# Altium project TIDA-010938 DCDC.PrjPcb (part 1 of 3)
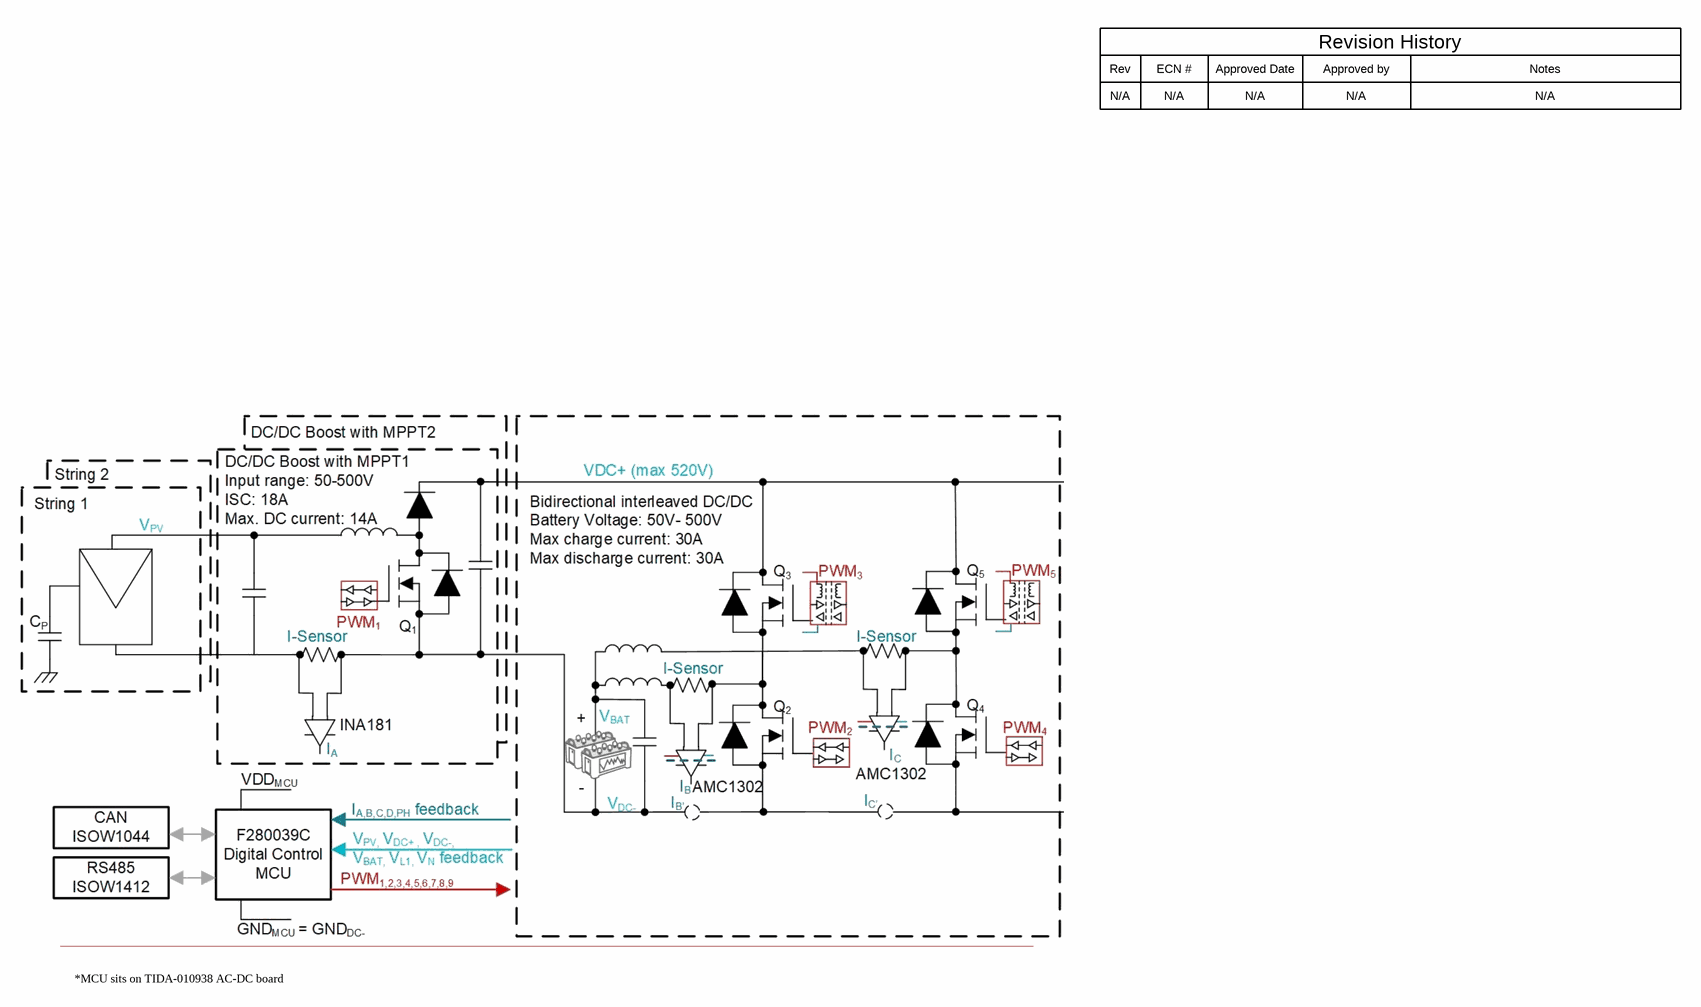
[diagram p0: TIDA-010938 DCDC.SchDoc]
CopyrightYear: 2024; PCB_Layout: Vedatroyee Ghosh; PCB_Rev: E2; PRJ_Customer: Public Release; PRJ_Engineer: Vedatroyee Ghosh; PRJ_Number: TIDA-010938 DC-DC; PRJ_Title: TIDA-010938 DC-DC; SCH_Rev: E2; TechSupport: http://www.ti.com/support; TID: A0498176
9 sheets, 410 parts. Net scope: flat (ports and power ports of the same name join across sheets).
Board file: TIDA-010938 DCDC.PcbDoc
Sheets:
  TIDA-010938 DCDC.SchDoc
    Designator = TIDA-010938 DCDC_Top.SchDoc
      Designator = TIDA-010938 DC-DC_Boost1.SchDoc
      Designator = TIDA-010938 DC-DC_Boost2.SchDoc
      Designator = TIDA-010938 bidirectional DC-DC_Interleaved1.SchDoc
      Designator = TIDA-010938 DC-DC_VoltageMeasurement.SchDoc
      Designator = TIDA-010938 DC-DC_Data conditionning.SchDoc
      Designator = TIDA-010938 bidirectional DC-DC_Interleaved2.SchDoc
      Designator = TIDA-010938 DCDC_Hardware.SchDoc

## Sheet TIDA-010938 DCDC.SchDoc
size 431 x 279 mm; Date: Not shown in title block; ApprovedBy: Not shown in title block; CheckedBy: Not shown in title block; Author: Not shown in title block; CompanyName: Not shown in title block; Engineer: Not shown in title block; Organization: Not shown in title block; Address1: Not shown in title block; Address2: Not shown in title block; Address3: Not shown in title block; Address4: Not shown in title block; DocumentNumber: 1; Revision: Use project parameter SCH_Rev; SheetNumber: 1; SheetTotal: 9; PageSetup: Record=PageOptions¦CenterHorizontal=True¦CenterVertical=True¦PrintScale=1.00¦XCorrection=1.00¦YCorrection=1.00¦PrintKind=0¦BorderSize=5000000¦LeftOffset=0¦BottomOffset=0¦Orientation=2¦PaperLength=1000¦PaperWidth=1000¦Scale=100¦PaperSource=15¦PrintQuality=600¦MediaType=1¦DitherType=10¦PaperKind=Letter¦PrintScaleMode=1

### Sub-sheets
Designator = TIDA-010938 DCDC_Top.SchDoc: no entries

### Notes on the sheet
- Rev
- N/A
- ECN #
- Approved Date
- Approved by
- Revision History
- Notes
- *MCU sits on TIDA-010938 AC-DC board

## Sheet TIDA-010938 DCDC_Top.SchDoc
size 431 x 279 mm; Date: Not shown in title block; ApprovedBy: Not shown in title block; CheckedBy: Not shown in title block; Author: Not shown in title block; CompanyName: Not shown in title block; Engineer: Not shown in title block; Organization: Not shown in title block; Address1: Not shown in title block; Address2: Not shown in title block; Address3: Not shown in title block; Address4: Not shown in title block; DocumentNumber: 1; Revision: Use project parameter SCH_Rev; SheetNumber: 2; SheetTotal: 9; PageSetup: Record=PageOptions¦CenterHorizontal=True¦CenterVertical=True¦PrintScale=1.00¦XCorrection=1.00¦YCorrection=1.00¦PrintKind=0¦BorderSize=5000000¦LeftOffset=0¦BottomOffset=0¦Orientation=2¦PaperLength=1000¦PaperWidth=1000¦Scale=100¦PaperSource=15¦PrintQuality=600¦MediaType=1¦DitherType=10¦PaperKind=Letter¦PrintScaleMode=1
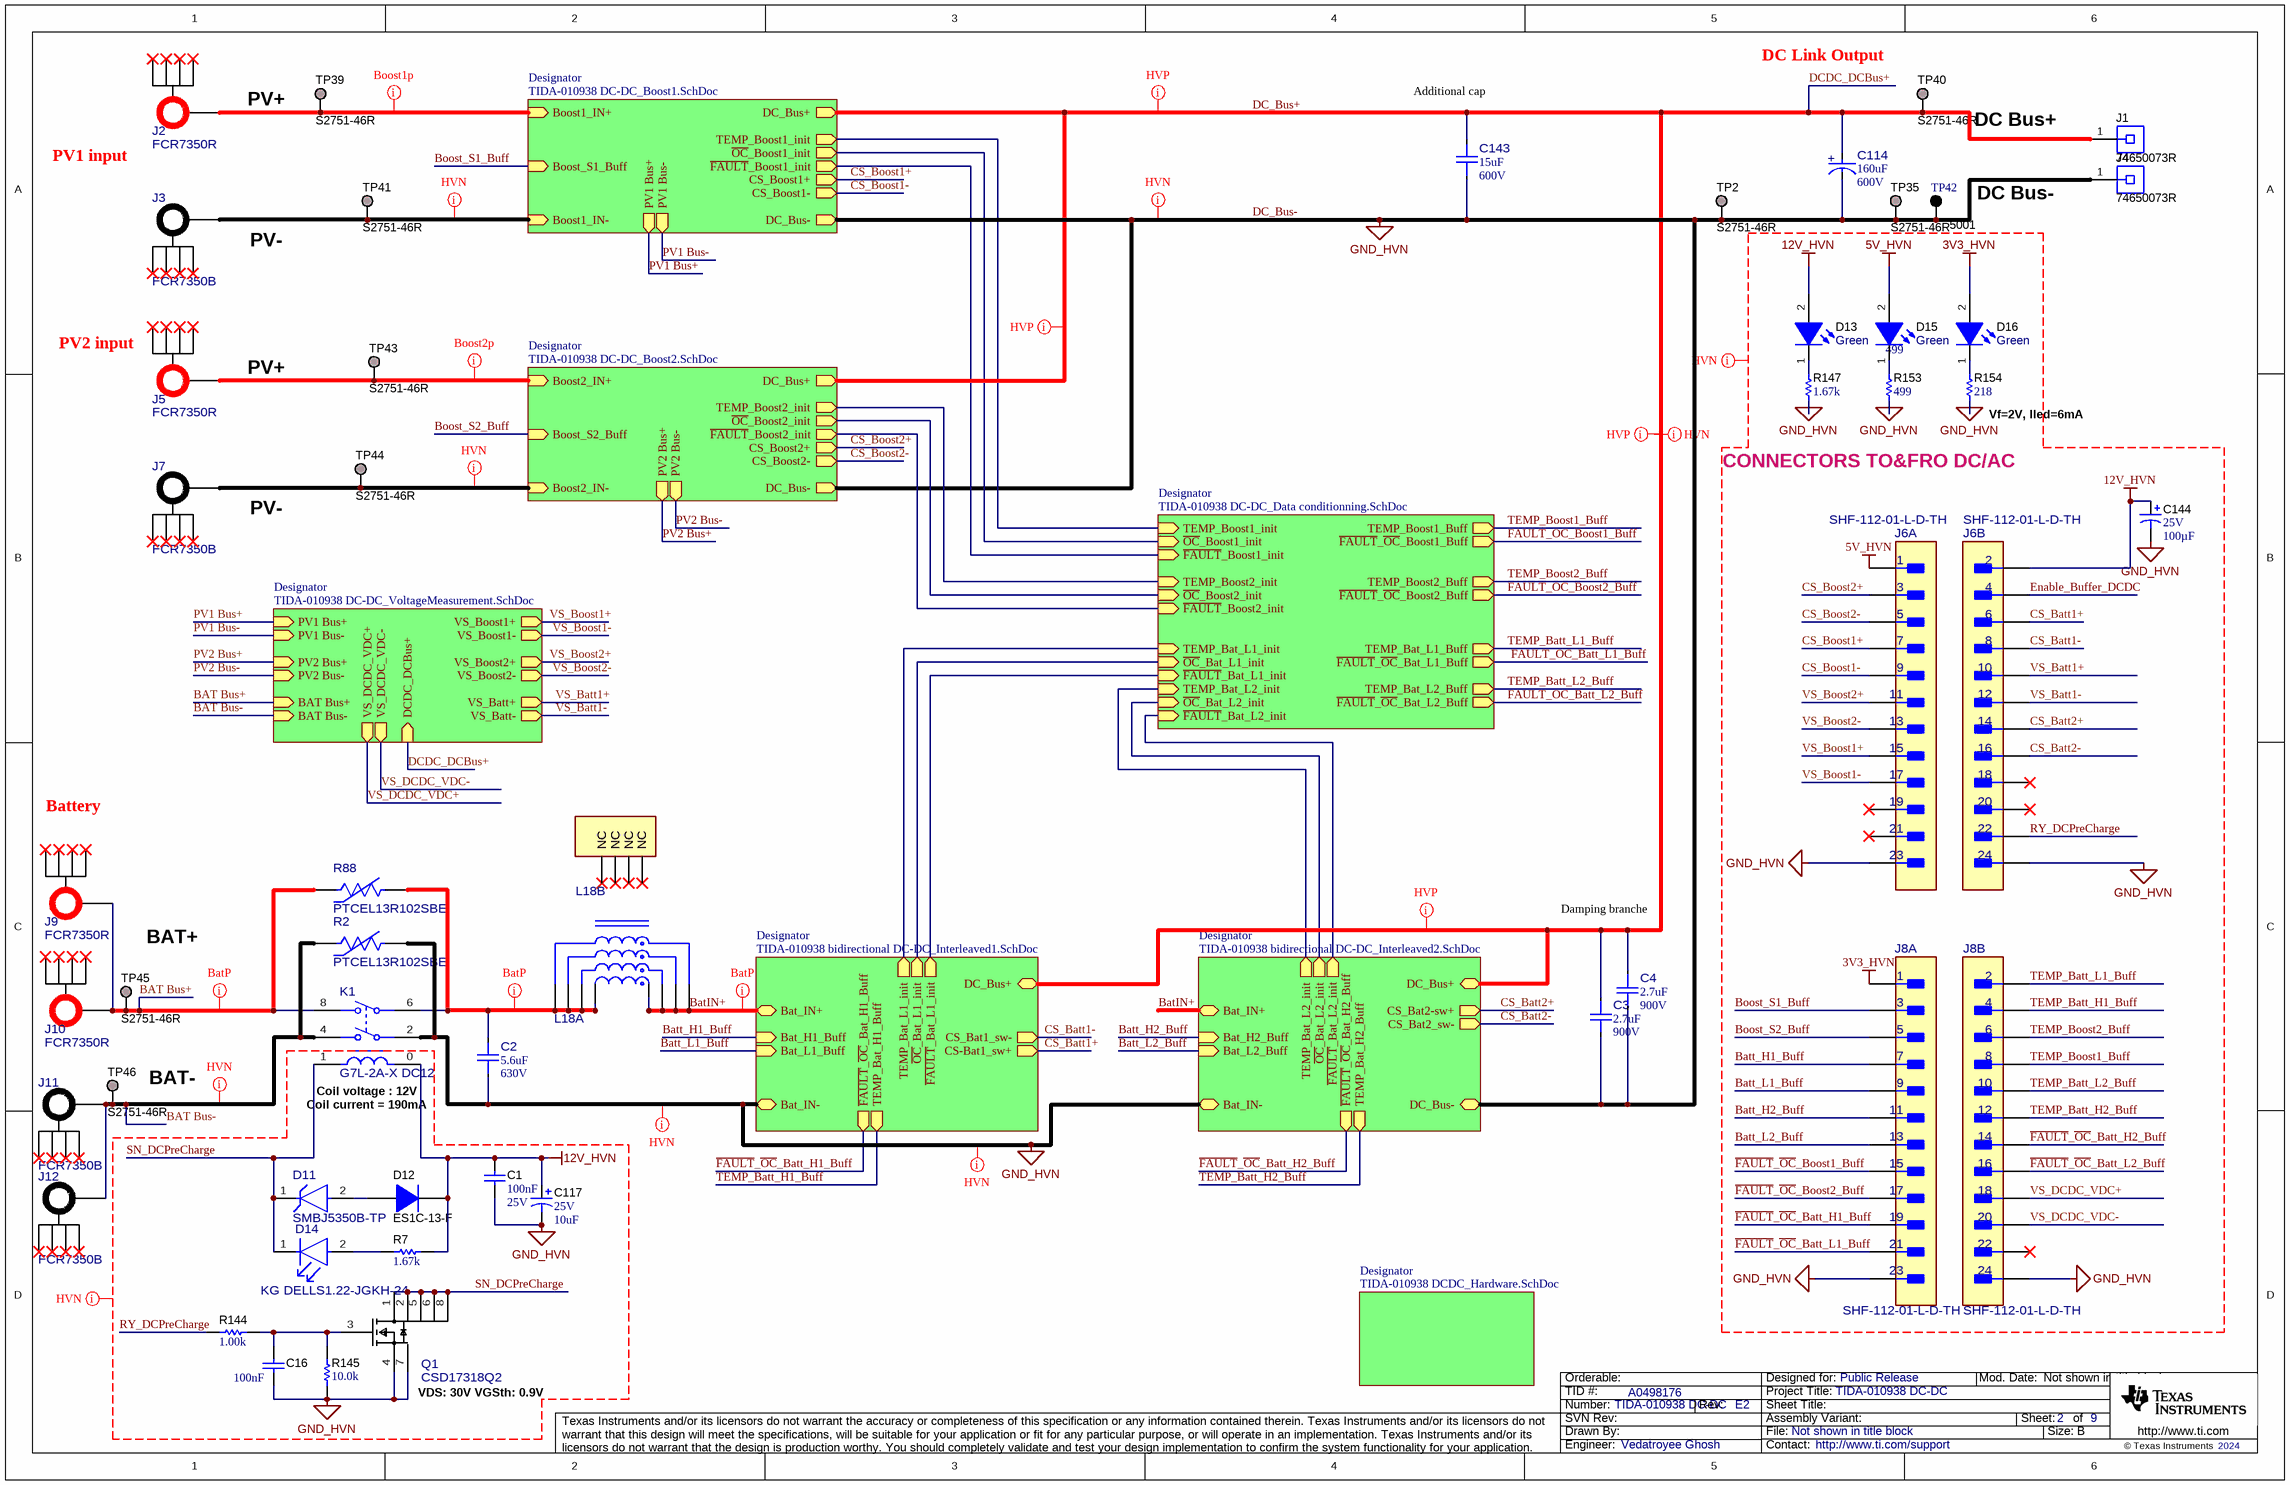
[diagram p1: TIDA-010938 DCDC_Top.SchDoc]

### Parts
C1  Cap_F: 100nF  VDC_V: 25V  [0603]  (hidden comment: 06033C104JAT2A)
C2  ValueDisplayed: 5.6uF  VDC_V: 630V  [FP-R533R456050P0M_RADIAL-MFG]  (hidden comment: R533R456050P0M)
C3  ValueDisplayed: 2.7uF  VDC_V: 900V  [FP-C4AKOBU4270A3YJ_RADIAL-MFG]  (hidden comment: C4AKOBU4270A3YJ)
C4  ValueDisplayed: 2.7uF  VDC_V: 900V  [FP-C4AKOBU4270A3YJ_RADIAL-MFG]  (hidden comment: C4AKOBU4270A3YJ)
C16  Cap_F: 100nF  [0603]  (hidden comment: GRM188R72A104KA35J)
C114  ValueDisplayed: 160uF  VDC_V: 600V  [FP-ALH82D161DD600_RADIAL-MFG]  (hidden comment: ALH82D161DD600)
C117  VDC_V: 25V  ValueDisplayed: 10uF  [SM_RADIAL_8MM]  (hidden comment: 25SVP10M)
C143  ValueDisplayed: 15uF  VDC_V: 600V  [FP-C4AQHBU5150P12J_RADIAL-MFG]  (hidden comment: C4AQHBU5150P12J)
C144  VDC_V: 25V  ValueDisplayed: 100µF  [UWT_630x770]  (hidden comment: UWT1E101MCL1GS)
D11  SMBJ5350B-TP  [FP-SMBJ5350B-TP_SMB-MFG]
D12  ES1C-13-F  [SMA]
D13  value Green  [WL-SMCW_GREEN]  (hidden comment: 150060VS75000)
D14  KG DELLS1.22-JGKH-24  [FP-KG DELLS1.22-JGKH-24_0603-MFG]
D15  value Green  [WL-SMCW_GREEN]  (hidden comment: 150060VS75000)
D16  value Green  [WL-SMCW_GREEN]  (hidden comment: 150060VS75000)
J1  74650073R  [Wurth_WP-THRBU]
J2  FCR7350R  [FP-FCR7350R_CONN_BANANA_JACK-MFG]
J3  FCR7350B  [FP-FCR7350B_CONN_BANANA_JACK-MFG]
J4  74650073R  [Wurth_WP-THRBU]
J5  FCR7350R  [FP-FCR7350R_CONN_BANANA_JACK-MFG]
J6  SHF-112-01-L-D-TH  [FP-SHF-112-01-L-D-TH_HDR24-MFG]  (parts A,B of 2)
J7  FCR7350B  [FP-FCR7350B_CONN_BANANA_JACK-MFG]
J8  SHF-112-01-L-D-TH  [FP-SHF-112-01-L-D-TH_HDR24-MFG]  (parts A,B of 2)
J9  FCR7350R  [FP-FCR7350R_CONN_BANANA_JACK-MFG]
J10  FCR7350R  [FP-FCR7350R_CONN_BANANA_JACK-MFG]
J11  FCR7350B  [FP-FCR7350B_CONN_BANANA_JACK-MFG]
J12  FCR7350B  [FP-FCR7350B_CONN_BANANA_JACK-MFG]
K1  G7L-2A-X DC12  [FP-G7L-2A-X DC12_PTH_RELAY_52MM5_35MM5-MFG]
L18  145454  [FP-145454_PTH12-MFG]  (value not drawn)  (parts A,B of 2)
Q1  CSD17318Q2  [FP-CSD17318Q2_WSON6-MFG]
R2  PTCEL13R102SBE  [FP-PTCEL13R102SBE_RADIAL-MFG]
R7  ValueDisplayed: 1.67k  [0603]  (hidden comment: RT0603DRE071K67L)
R88  PTCEL13R102SBE  [FP-PTCEL13R102SBE_RADIAL-MFG]
R144  ValueDisplayed: 1.00k  [0603]  (hidden comment: RNCF0603TKY1K00)
R145  ValueDisplayed: 10.0k  [0603]  (hidden comment: RG1608P-103-B-T5)
R147  ValueDisplayed: 1.67k  [0603]  (hidden comment: RT0603DRE071K67L)
R153  value 499  [0603]  (hidden comment: CRCW0603499RFKEAC)
R154  ValueDisplayed: 218  [0603]  (hidden comment: RT0603DRE07218RL)
TP2  S2751-46R  [Harwin_S2751-46R]  (no BOM)
TP35  S2751-46R  [Harwin_S2751-46R]  (no BOM)
TP39  S2751-46R  [Harwin_S2751-46R]  (no BOM)
TP40  S2751-46R  [Harwin_S2751-46R]  (no BOM)
TP41  S2751-46R  [Harwin_S2751-46R]  (no BOM)
TP42  5001  [Keystone5001]
TP43  S2751-46R  [Harwin_S2751-46R]  (no BOM)
TP44  S2751-46R  [Harwin_S2751-46R]  (no BOM)
TP45  S2751-46R  [Harwin_S2751-46R]  (no BOM)
TP46  S2751-46R  [Harwin_S2751-46R]  (no BOM)

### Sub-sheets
Designator = TIDA-010938 DC-DC_Boost1.SchDoc: Boost_S1_Buff (in), TEMP_Boost1_init (out), ~{FAULT}_Boost1_init (out), ~{OC}_Boost1_init (out), DC_Bus+ (out), DC_Bus- (out), Boost1_IN+ (in), Boost1_IN- (in), CS_Boost1+ (out), CS_Boost1- (out), PV1 Bus+ (out), PV1 Bus- (out)
Designator = TIDA-010938 DC-DC_Boost2.SchDoc: DC_Bus+ (out), DC_Bus- (out), Boost_S2_Buff (in), TEMP_Boost2_init (out), ~{FAULT}_Boost2_init (out), ~{OC}_Boost2_init (out), Boost2_IN+ (in), Boost2_IN- (in), CS_Boost2+ (out), CS_Boost2- (out), PV2 Bus+ (out), PV2 Bus- (out)
Designator = TIDA-010938 bidirectional DC-DC_Interleaved1.SchDoc: DC_Bus+ (bidir), Bat_IN+ (bidir), Bat_IN- (bidir), Bat_L1_Buff (in), Bat_H1_Buff (in), ~{FAULT}_Bat_L1_init (out), ~{FAULT}_~{OC}_Bat_H1_Buff (out), ~{OC}_Bat_L1_init (out), TEMP_Bat_H1_Buff (out), TEMP_Bat_L1_init (out), CS_Bat1_sw- (out), CS-Bat1_sw+ (out)
Designator = TIDA-010938 DC-DC_VoltageMeasurement.SchDoc: PV1 Bus+ (in), PV2 Bus+ (in), VS_Boost2+ (out), BAT Bus+ (in), BAT Bus- (in), VS_Batt+ (out), VS_Boost1+ (out), VS_Batt- (out), VS_Boost2- (out), VS_Boost1- (out), PV2 Bus- (in), PV1 Bus- (in), DCDC_DCBus+ (in), VS_DCDC_VDC+ (out), VS_DCDC_VDC- (out)
Designator = TIDA-010938 DC-DC_Data conditionning.SchDoc: ~{FAULT}_Boost1_init (in), ~{OC}_Boost1_init (in), ~{FAULT}_Boost2_init (in), ~{OC}_Boost2_init (in), ~{FAULT}_Bat_L1_init (in), ~{OC}_Bat_L1_init (in), ~{FAULT}_Bat_L2_init (in), ~{OC}_Bat_L2_init (in), TEMP_Boost1_init (in), TEMP_Boost2_init (in), TEMP_Bat_L1_init (in), TEMP_Bat_L2_init (in), TEMP_Boost1_Buff (out), ~{FAULT}_~{OC}_Boost1_Buff (out), TEMP_Boost2_Buff (out), ~{FAULT}_~{OC}_Boost2_Buff (out), TEMP_Bat_L1_Buff (out), ~{FAULT}_~{OC}_Bat_L1_Buff (out), TEMP_Bat_L2_Buff (out), ~{FAULT}_~{OC}_Bat_L2_Buff (out)
Designator = TIDA-010938 bidirectional DC-DC_Interleaved2.SchDoc: DC_Bus+ (bidir), DC_Bus- (bidir), Bat_IN+ (bidir), Bat_IN- (bidir), Bat_L2_Buff (in), Bat_H2_Buff (in), TEMP_Bat_H2_Buff (out), ~{FAULT}_~{OC}_Bat_H2_Buff (out), ~{FAULT}_Bat_L2_init (out), ~{OC}_Bat_L2_init (out), TEMP_Bat_L2_init (out), CS_Bat2-sw+ (out), CS_Bat2_sw- (out)
Designator = TIDA-010938 DCDC_Hardware.SchDoc: no entries

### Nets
3V3_HVN: D16.2(A) J8.1
5V_HVN: D15.2(A) J6.1
12V_HVN: C1.2 C117.1(+) C144.1(+) D12.1(K) D13.2(A) J6.2 K1.0 R7.1
DC_Bus-: C1.1 C2.1 C3.2 C4.2 C16.2 C114.1(CATHODE) C117.2(-) C143.1 C144.2(-) J4.1 J6.23 J6.24 J8.23 J8.24 K1.2 Q1.4(S) Q1.7(S) R2.2 R145.2 R147.1 R153.1 R154.1 TP2.1 TP35.1 TP42.1 ; sheet Designator/DC_Bus-, sheet Designator/DC_Bus-, sheet Designator/Bat_IN-, sheet Designator/DC_Bus-, sheet Designator/Bat_IN-  [also labelled GND_HVN]
BAT Bus+: J9.1 J10.1 K1.8 R88.1 TP45.1 ; sheet Designator/BAT Bus+
BAT Bus-: J11.1 J12.1 K1.4 R2.1 TP46.1 ; sheet Designator/BAT Bus-
BatIN+: L18.1 L18.2 L18.3 L18.4 ; sheet Designator/Bat_IN+, sheet Designator/Bat_IN+
Batt_H1_Buff: J8.7 ; sheet Designator/Bat_H1_Buff
Batt_H2_Buff: J8.11 ; sheet Designator/Bat_H2_Buff
Batt_L1_Buff: J8.9 ; sheet Designator/Bat_L1_Buff
Batt_L2_Buff: J8.13 ; sheet Designator/Bat_L2_Buff
Boost_S1_Buff: J8.3 ; sheet Designator/Boost_S1_Buff
Boost_S2_Buff: J8.5 ; sheet Designator/Boost_S2_Buff
CS_Batt1+: J6.6 ; sheet Designator/CS-Bat1_sw+
CS_Batt1-: J6.8 ; sheet Designator/CS_Bat1_sw-
CS_Batt2+: J6.14 ; sheet Designator/CS_Bat2-sw+
CS_Batt2-: J6.16 ; sheet Designator/CS_Bat2_sw-
CS_Boost1+: J6.7 ; sheet Designator/CS_Boost1+
CS_Boost1-: J6.9 ; sheet Designator/CS_Boost1-
CS_Boost2+: J6.3 ; sheet Designator/CS_Boost2+
CS_Boost2-: J6.5 ; sheet Designator/CS_Boost2-
DC_Bus+: C3.1 C4.1 C114.2(ANODE) C143.2 J1.1 TP40.1 ; sheet Designator/DC_Bus+, sheet Designator/DC_Bus+, sheet Designator/DC_Bus+, sheet Designator/DCDC_DCBus+, sheet Designator/DC_Bus+  [also labelled DCDC_DCBus+]
Enable_Buffer_DCDC: J6.4
~{FAULT}_~{OC}_Batt_H1_Buff: J8.19 ; sheet Designator/~{FAULT}_~{OC}_Bat_H1_Buff
~{FAULT}_~{OC}_Batt_H2_Buff: J8.14 ; sheet Designator/~{FAULT}_~{OC}_Bat_H2_Buff
~{FAULT}_~{OC}_Batt_L1_Buff: J8.21 ; sheet Designator/~{FAULT}_~{OC}_Bat_L1_Buff
~{FAULT}_~{OC}_Batt_L2_Buff: J8.16 ; sheet Designator/~{FAULT}_~{OC}_Bat_L2_Buff
~{FAULT}_~{OC}_Boost1_Buff: J8.15 ; sheet Designator/~{FAULT}_~{OC}_Boost1_Buff
~{FAULT}_~{OC}_Boost2_Buff: J8.17 ; sheet Designator/~{FAULT}_~{OC}_Boost2_Buff
PV1 Bus+: sheet Designator/PV1 Bus+, sheet Designator/PV1 Bus+
PV1 Bus-: sheet Designator/PV1 Bus-, sheet Designator/PV1 Bus-
PV2 Bus+: sheet Designator/PV2 Bus+, sheet Designator/PV2 Bus+
PV2 Bus-: sheet Designator/PV2 Bus-, sheet Designator/PV2 Bus-
RY_DCPreCharge: J6.22 R144.1
SN_DCPreCharge: D11.1(CATHODE) D14.1(CATHODE) K1.1 Q1.1(D) Q1.2(D) Q1.5(D) Q1.6(D) Q1.8(D)
TEMP_Batt_H1_Buff: J8.4 ; sheet Designator/TEMP_Bat_H1_Buff
TEMP_Batt_H2_Buff: J8.12 ; sheet Designator/TEMP_Bat_H2_Buff
TEMP_Batt_L1_Buff: J8.2 ; sheet Designator/TEMP_Bat_L1_Buff
TEMP_Batt_L2_Buff: J8.10 ; sheet Designator/TEMP_Bat_L2_Buff
TEMP_Boost1_Buff: J8.8 ; sheet Designator/TEMP_Boost1_Buff
TEMP_Boost2_Buff: J8.6 ; sheet Designator/TEMP_Boost2_Buff
VS_Batt1+: J6.10 ; sheet Designator/VS_Batt+
VS_Batt1-: J6.12 ; sheet Designator/VS_Batt-
VS_Boost1+: J6.15 ; sheet Designator/VS_Boost1+
VS_Boost1-: J6.17 ; sheet Designator/VS_Boost1-
VS_Boost2+: J6.11 ; sheet Designator/VS_Boost2+
VS_Boost2-: J6.13 ; sheet Designator/VS_Boost2-
VS_DCDC_VDC+: J8.18 ; sheet Designator/VS_DCDC_VDC+
VS_DCDC_VDC-: J8.20 ; sheet Designator/VS_DCDC_VDC-
NetC2_2: C2.2 K1.6 L18.9 L18.10 L18.11 L18.12 R88.2
NetC16_1: C16.1 Q1.3(G) R144.2 R145.1
NetD11_2: D11.2(ANODE) D12.2(A)
NetD13_1: D13.1(K) R147.2
NetD14_2: D14.2(ANODE) R7.2
NetD15_1: D15.1(K) R153.2
NetD16_1: D16.1(K) R154.2
NetJ2_1: J2.1 TP39.1 ; sheet Designator/Boost1_IN+
NetJ3_1: J3.1 TP41.1 ; sheet Designator/Boost1_IN-
NetJ5_1: J5.1 TP43.1 ; sheet Designator/Boost2_IN+
NetJ7_1: J7.1 TP44.1 ; sheet Designator/Boost2_IN-
(unnamed): sheet Designator/TEMP_Boost1_init, sheet Designator/TEMP_Boost1_init
(unnamed): sheet Designator/~{FAULT}_Boost1_init, sheet Designator/~{FAULT}_Boost1_init  [a separate net that carries the same name]
(unnamed): sheet Designator/~{OC}_Boost1_init, sheet Designator/~{OC}_Boost1_init  [a separate net that carries the same name]
(unnamed): sheet Designator/TEMP_Boost2_init, sheet Designator/TEMP_Boost2_init  [a separate net that carries the same name]
(unnamed): sheet Designator/~{FAULT}_Boost2_init, sheet Designator/~{FAULT}_Boost2_init  [a separate net that carries the same name]
(unnamed): sheet Designator/~{OC}_Boost2_init, sheet Designator/~{OC}_Boost2_init  [a separate net that carries the same name]
(unnamed): sheet Designator/~{FAULT}_Bat_L1_init, sheet Designator/~{FAULT}_Bat_L1_init  [a separate net that carries the same name]
(unnamed): sheet Designator/~{OC}_Bat_L1_init, sheet Designator/~{OC}_Bat_L1_init  [a separate net that carries the same name]
(unnamed): sheet Designator/TEMP_Bat_L1_init, sheet Designator/TEMP_Bat_L1_init  [a separate net that carries the same name]
(unnamed): sheet Designator/~{FAULT}_Bat_L2_init, sheet Designator/~{FAULT}_Bat_L2_init  [a separate net that carries the same name]
(unnamed): sheet Designator/~{OC}_Bat_L2_init, sheet Designator/~{OC}_Bat_L2_init  [a separate net that carries the same name]
(unnamed): sheet Designator/TEMP_Bat_L2_init, sheet Designator/TEMP_Bat_L2_init  [a separate net that carries the same name]

Not connected (* = marked no-connect by the designer): J2 2(MNT_1)* 3(MNT_2)* 4(MNT_3)* 5(MNT_4)*; J3 2(MNT_1)* 3(MNT_2)* 4(MNT_3)* 5(MNT_4)*; J5 2(MNT_1)* 3(MNT_2)* 4(MNT_3)* 5(MNT_4)*; J6 18* 19* 20* 21*; J7 2(MNT_1)* 3(MNT_2)* 4(MNT_3)* 5(MNT_4)*; J8 22*; J9 2(MNT_1)* 3(MNT_2)* 4(MNT_3)* 5(MNT_4)*; J10 2(MNT_1)* 3(MNT_2)* 4(MNT_3)* 5(MNT_4)*; J11 2(MNT_1)* 3(MNT_2)* 4(MNT_3)* 5(MNT_4)*; J12 2(MNT_1)* 3(MNT_2)* 4(MNT_3)* 5(MNT_4)*; L18 5(NC)* 6(NC)* 7(NC)* 8(NC)*

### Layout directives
net class HVN: 3V3_HVN, 5V_HVN, 12V_HVN, (no net found under the mark), BAT Bus-, Batt_H1_Buff, Batt_H2_Buff, Batt_L1_Buff, Batt_L2_Buff, Boost_S1_Buff, Boost_S2_Buff, CS_Batt1+, CS_Batt1-, CS_Batt2+, CS_Batt2-, CS_Boost1+, CS_Boost1-, CS_Boost2+, CS_Boost2-, DC_Bus-, Enable_Buffer_DCDC, GND_HVN, NetJ3_1, NetJ7_1, RY_DCPreCharge, SN_DCPreCharge, TEMP_Batt_H1_Buff, TEMP_Batt_H2_Buff, TEMP_Batt_L1_Buff, TEMP_Batt_L2_Buff, TEMP_Boost1_Buff, TEMP_Boost2_Buff, VS_Batt1+, VS_Batt1-, VS_Boost1+, VS_Boost1-, VS_Boost2+, VS_Boost2-, VS_DCDC_VDC+, VS_DCDC_VDC-, ~{FAULT}_~{OC}_Batt_H1_Buff, ~{FAULT}_~{OC}_Batt_H2_Buff, ~{FAULT}_~{OC}_Batt_L1_Buff, ~{FAULT}_~{OC}_Batt_L2_Buff, ~{FAULT}_~{OC}_Boost1_Buff, ~{FAULT}_~{OC}_Boost2_Buff
net class Boost1p: NetJ2_1
net class Boost2p: NetJ5_1
net class HVP: DC_Bus+
net class BatP: BAT Bus+, BatIN+, NetC2_2

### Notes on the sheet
- PV+
- (near C143) Additional cap
- DC Link Output
- PV1 input
- DC Bus+
- DC Bus-
- PV-
- (near J5) PV2 input
- (near R154) Vf=2V, Iled=6mA
- CONNECTORS TO&FRO DC/AC
- Battery
- BAT+
- Damping branche
- (near TP46) BAT-
- (near K1) Coil voltage : 12V
- (near K1) Coil current = 190mA
- (near Q1) VDS: 30V VGSth: 0.9V

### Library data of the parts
C1 = CMP-0006752-5: CAP, CERM, 0.1 uF, 25 V, +/- 5%, X7R, 0603; Manufacturer: AVX; TaMin_C: -55°C; ESR_ohm: 0.05; Polarized: N; SizeAreaWB_mm2: 4.68; Value1: 0.05 ohm; U/M: EA; Value: 0.1uF; TaMax_C: 125°C; SizeZ_mm: 1; SizeX_mm: 1.6; SizeY_mm: 0.8; SizeArea_mm2: 1.28; AEC Category: Q200
C2 = CMP-0045188-1: 5.6 µF Film Capacitor 310V 630V Polypropylene (PP), Metallized Radial; Manufacturer: KEMET; AEC Grade: Grade 3; AEC Qualified: Yes; Cap_F: 5.6µF; SizeZ_mm: 30.3mm; Tolerance_%: 20%; VAC_X: X2; Value: 5.6µF
C3 C4 = CMP-0045062-1: 2.7 µF Film Capacitor 900V Polypropylene (PP), Metallized Radial; Manufacturer: Kemet; AEC Grade: Grade 1; AEC Qualified: Yes; Cap_F: 2.7µF; SizeZ_mm: 28.7mm; Tolerance_%: 5%; Value: 2.7µF
C16 = CMP-0007470-5: CAP, CERM, 0.1 uF, 100 V, +/- 10%, X7R, 0603; Manufacturer: MuRata; TaMin_C: -55°C; Polarized: N; SizeAreaWB_mm2: 4.68; Value1: Unknown; U/M: EA; Value: 0.1uF; TaMax_C: 125°C; SizeZ_mm: 1; SizeX_mm: 1.6; SizeY_mm: 0.8; Value2: 100V; SizeArea_mm2: 1.28; AEC Category: Q200
C114 = CMP-0033686-1: ALH82, Aluminum Electrolytic, 160 uF, 20%, 600 VDC, -40/+105°C; Manufacturer: KEMET; AEC Qualified: No; Cap_F: 160µF; IRMS_A: 4.51A; SizeZ_mm: 42mm; Esr: 0.877; Leakage Current: 288uA; Life: 3000Hours; Value: 160µF
C117 = CMP-0012113-3: CAP, Aluminum Polymer, 10 uF, 25 V, +/- 20%, 0.06 ohm, 8x10 SMD; Manufacturer: Panasonic; TaMin_C: -55°C; ESR_ohm: 0.06; Polarized: Y; SizeAreaWB_mm2: 113.3; Value: 10uF; TaMax_C: 105°C; SizeZ_mm: 10.2; SizeX_mm: 9; SizeY_mm: 8.3; Cap_Case: 8.3x8.3x6.9; SizeArea_mm2: 74.7; CompType: Capacitor; Cap_F: 10µF; IRMS_A: 1.5A; AEC Category: Q200
C143 = CMP-0123402-1: 15 µF Film Capacitor 600V Polypropylene (PP), Metallized Radial; Manufacturer: KEMET; AEC Grade: Grade 1; AEC Qualified: Yes; Cap_F: 15µF; SizeZ_mm: 37.2mm; Tolerance_%: 5%; Value: 15µF
C144 = CMP-0081462-1: CAP, AL, 100 µF, 25 V, +/- 20%, SMD; Manufacturer: Nichicon; TaMin_C: -55°C; Polarized: Y; SizeAreaWB_mm2: 77.4; U/M: EA; Value: 100uF; TaMax_C: 105°C; SizeZ_mm: 8; SizeX_mm: 7; SizeY_mm: 6.6; Cap_Case: 6.3x7.7mm; SizeArea_mm2: 46.2; CompType: Capacitor; AEC Qualified: N; IRMS_A: 91mA; AEC Category: Q200
D11 = CMP-0097215-1: Zener Diode 13 V 5 W ±5% Surface Mount DO-214AA (SMB); Manufacturer: MCC; Power_W: 5W; Standoff Height: 0.05mm; Vr_V: 9.9V; SizeZ_mm: 2.62mm; Zener Impedance: 2.5Ω; AEC Qualified: No; Max Reverse Leakage Current: 1uA; Vz_V: 13V; Vf_V: 13.65V; TJmax_C: 150°C
D12 = CMP-0029023-2: Diode, Superfast Rectifier, 150 V, 1 A, SMA; Manufacturer: Diodes Inc.; TJmax_C: 150°C; Vr_V: 150V; Value2: 0.92V; SizeX_mm: 5.59; Green_REACh: Incomplete; SizeAreaWB_mm2: 37.3428; Value: 150V; Vf_V: 920mV; Green_Lifecycle: Not Set; Value1: 1A; SizeZ_mm: 2.87; SizeArea_mm2: 16.3228; SizeY_mm: 2.92; AEC Category: Q101; RJC_CperW: 25
D13 D15 D16 = CMP-0002894-2: LED, Green, SMD; Manufacturer: Wurth Elektronik; Type: AlInGaP; Value2: 2V; Io_A: 20mA; Value1: W
D14 = CMP-0093310-1: Standard LEDs - SMD Green TOPLED E 1608; Manufacturer: Osram Opto; AEC Grade: Grade 2; LambdaP: 572nm; SizeZ_mm: 0.7mm; LuminousFlux_PhiV: 0.016-0.0295lm; Luminous Intensity: 4.5-9.7mcd; LambdaD: 570nm; Tjmax_C: 125°C; Angle: 120°; Led Orientation: Top View; Forward Current: 2mA; Vf_V: 1.8V; AEC Qualified: Yes; Vr_V: 12V
J1 J4 = CMP-0078526-1: Power Element Bush, M3, TH; Manufacturer: Wurth Elektronik; Gender: Female; Current_A: 50A; ContactFinish: Tin; CompType: Screw Terminal
J2 J5 J9 J10 = CMP-0032022-2: Banana Jack Connector Standard Banana Solder Red; Manufacturer: CLIFF Electronic Components; ContactFinish: Gold; Current_A: 24A; Voltage_V: 1kV; AEC Qualified: No; Conn Orientation: Horizontal; Is Female: yes; SizeZ_mm: 12.5mm; Standoff Height: 0.7mm
J3 J7 J11 J12 = CMP-0032021-2: Banana Jack Connector Standard Banana Solder Black; Manufacturer: CLIFF Electronic Components; ContactFinish: Gold; Current_A: 24A; Voltage_V: 1kV; AEC Qualified: No; Conn Orientation: Horizontal; Is Female: yes; SizeZ_mm: 12.5mm; Standoff Height: 0.7mm
J6 J8 = CMP-0003796-1: Conn Shrouded Header (4 Sides) HDR 24 POS 1.27mm Solder ST Top Entry Thru-Hole Tube; Manufacturer: Samtec; ContactFinish: Gold,Nickel; Row_Count: 2; AEC Qualified: No; Conn Gender: Male; Conn Orientation: Straight; SizeZ_mm: 5.46mm; Standoff Height: 0.38mm
K1 = CMP-0093885-1: General Purpose Relay DPST-NO (2 Form A) 12VDC Coil Through Hole; Manufacturer: Omron; SizeZ_mm: 41mm; Coil Power_W: 2.3W; TaMax_C: +85°C; Switching Current: 30A; TaMin_C: -40°C; Coil Voltage_VDC: 12V; Coil Current_A: 191.7mA; Coil Resistance: 63Ω; Coil Type: Non-Latching; AEC Qualified: No
L18 = CMP-0123020-1: Inductor 22 μH 10% 5mΩ; Manufacturer: Bourns; AEC Qualified: No; DCR_ohm: 5.5m; Ind_H: 22µH; Isat: 35A; SizeZ_mm: 40.9mm; Value: 22uH; Test Frequency: 100kHz
Q1 = CMP-0076725-1: 30-V N-Channel NexFET™ Power MOSFET; Manufacturer: Texas Instruments; VdsMax_V: 30V; SizeZ_mm: 0.8mm; ChMode: False; QgTyp_nC: 6nC @ 4.5V; Rdson45_ohm: 0.0139; Vgs_V: 10V; AEC Qualified: No; IdsMax_A: 10A
R2 R88 = CMP-0043438-1: PTCEL Series 850 V 1 kOhm ±30 % Radial Inrush Current Limiter PTC Thermistor; Manufacturer: Vishay; SizeZ_mm: 17mm; Value: 1000Ω; AEC Grade: Grade 2; AEC Qualified: Yes; Hold Current: 30mA; Max Current: 40A; Standoff Height: 2mm; Tolerance_%: 30%; VDC_V: 850V
R7 R147 = CMP-0024836-3: RES, 1.67 k, 0.5%, 0.1 W, 0603; Manufacturer: Yageo America; Power_W: 100mW; TempCo: 50 ppm/C; Value_Code: 1k67; U/M: EA; Value: 1.67k; EIA_Code: E192; SizeX_mm: 1.6; SizeY_mm: 0.8; SizeZ_mm: 1; Value2: 0.1W; SizeArea_mm2: 1.28; VDC_V: 75V; AEC Category: Q200
R144 = CMP-0023627-2: RES, 1.00 k, 0.01%, 0.063 W, 0603; Manufacturer: Stackpole Electronics Inc; Power_W: 63mW; TempCo: 5 ppm/C; Value_Code: 1k00; U/M: EA; Value: 1.00k; Res_ohm: 1k; SizeX_mm: 1.6; SizeY_mm: 0.8; SizeZ_mm: 1; Value2: 0.063W; SizeArea_mm2: 1.28; VDC_V: 50V; AEC Category: Q200
R145 = CMP-0023404-1: RES, 10.0 k, 0.1%, 0.1 W, 0603; Manufacturer: Susumu Co Ltd; Power_W: 100mW; TempCo: 25 ppm/C; Value_Code: 10k0; U/M: EA; Value: 10.0k; EIA_Code: E192; Res_ohm: 10k; SizeX_mm: 1.6; SizeY_mm: 0.8; SizeZ_mm: 1; Value2: 0.1W; SizeArea_mm2: 1.28; VDC_V: 75V; AEC Category: Q200
R153 = CMP-0082532-1: RES, 499, 1%, 0.1 W, 0603; Manufacturer: Vishay-Dale; Power_W: 100mW; TempCo: 100 ppm/C; SizeAreaWB_mm2: 4.68; Value_Code: 499R; EIA_Code: E96; SizeX_mm: 1.6; SizeY_mm: 0.8; SizeZ_mm: 1; Value2: 0.1W; SizeArea_mm2: 1.28; AEC Qualified: N; VDC_V: 75V; AEC Category: Q200
R154 = CMP-0024934-2: RES, 218, 0.5%, 0.1 W, 0603; Manufacturer: Yageo America; Power_W: 100mW; TempCo: 50 ppm/C; Value_Code: 218R; U/M: EA; Value: 218; EIA_Code: E192; SizeX_mm: 1.6; SizeY_mm: 0.8; SizeZ_mm: 1; Value2: 0.1W; SizeArea_mm2: 1.28; VDC_V: 75V; AEC Category: Q200
TP2 TP35 TP39-TP41 TP43-TP46 = CMP-0003968-1: Test Point, SMT; Manufacturer: Harwin
TP42 = CMP-0055138-2: Test Point, Miniature, Black, TH; Manufacturer: Keystone Electronics; ContactFinish: Silver; CNHeader: FALSE; Green_Lifecycle: Active; Green_REACh: Passed; CT: TRUE

## Sheet TIDA-010938 DC-DC_Boost1.SchDoc
size 431 x 279 mm; Date: Not shown in title block; ApprovedBy: Not shown in title block; CheckedBy: Not shown in title block; Author: Not shown in title block; CompanyName: Not shown in title block; Engineer: Not shown in title block; Organization: Not shown in title block; Address1: Not shown in title block; Address2: Not shown in title block; Address3: Not shown in title block; Address4: Not shown in title block; DocumentNumber: 1; Revision: Use project parameter SCH_Rev; SheetNumber: 3; SheetTotal: 9; PageSetup: Record=PageOptions¦CenterHorizontal=True¦CenterVertical=True¦PrintScale=1.00¦XCorrection=1.00¦YCorrection=1.00¦PrintKind=0¦BorderSize=5000000¦LeftOffset=0¦BottomOffset=0¦Orientation=2¦PaperLength=1000¦PaperWidth=1000¦Scale=100¦PaperSource=15¦PrintQuality=600¦MediaType=1¦DitherType=10¦PaperKind=Letter¦PrintScaleMode=1
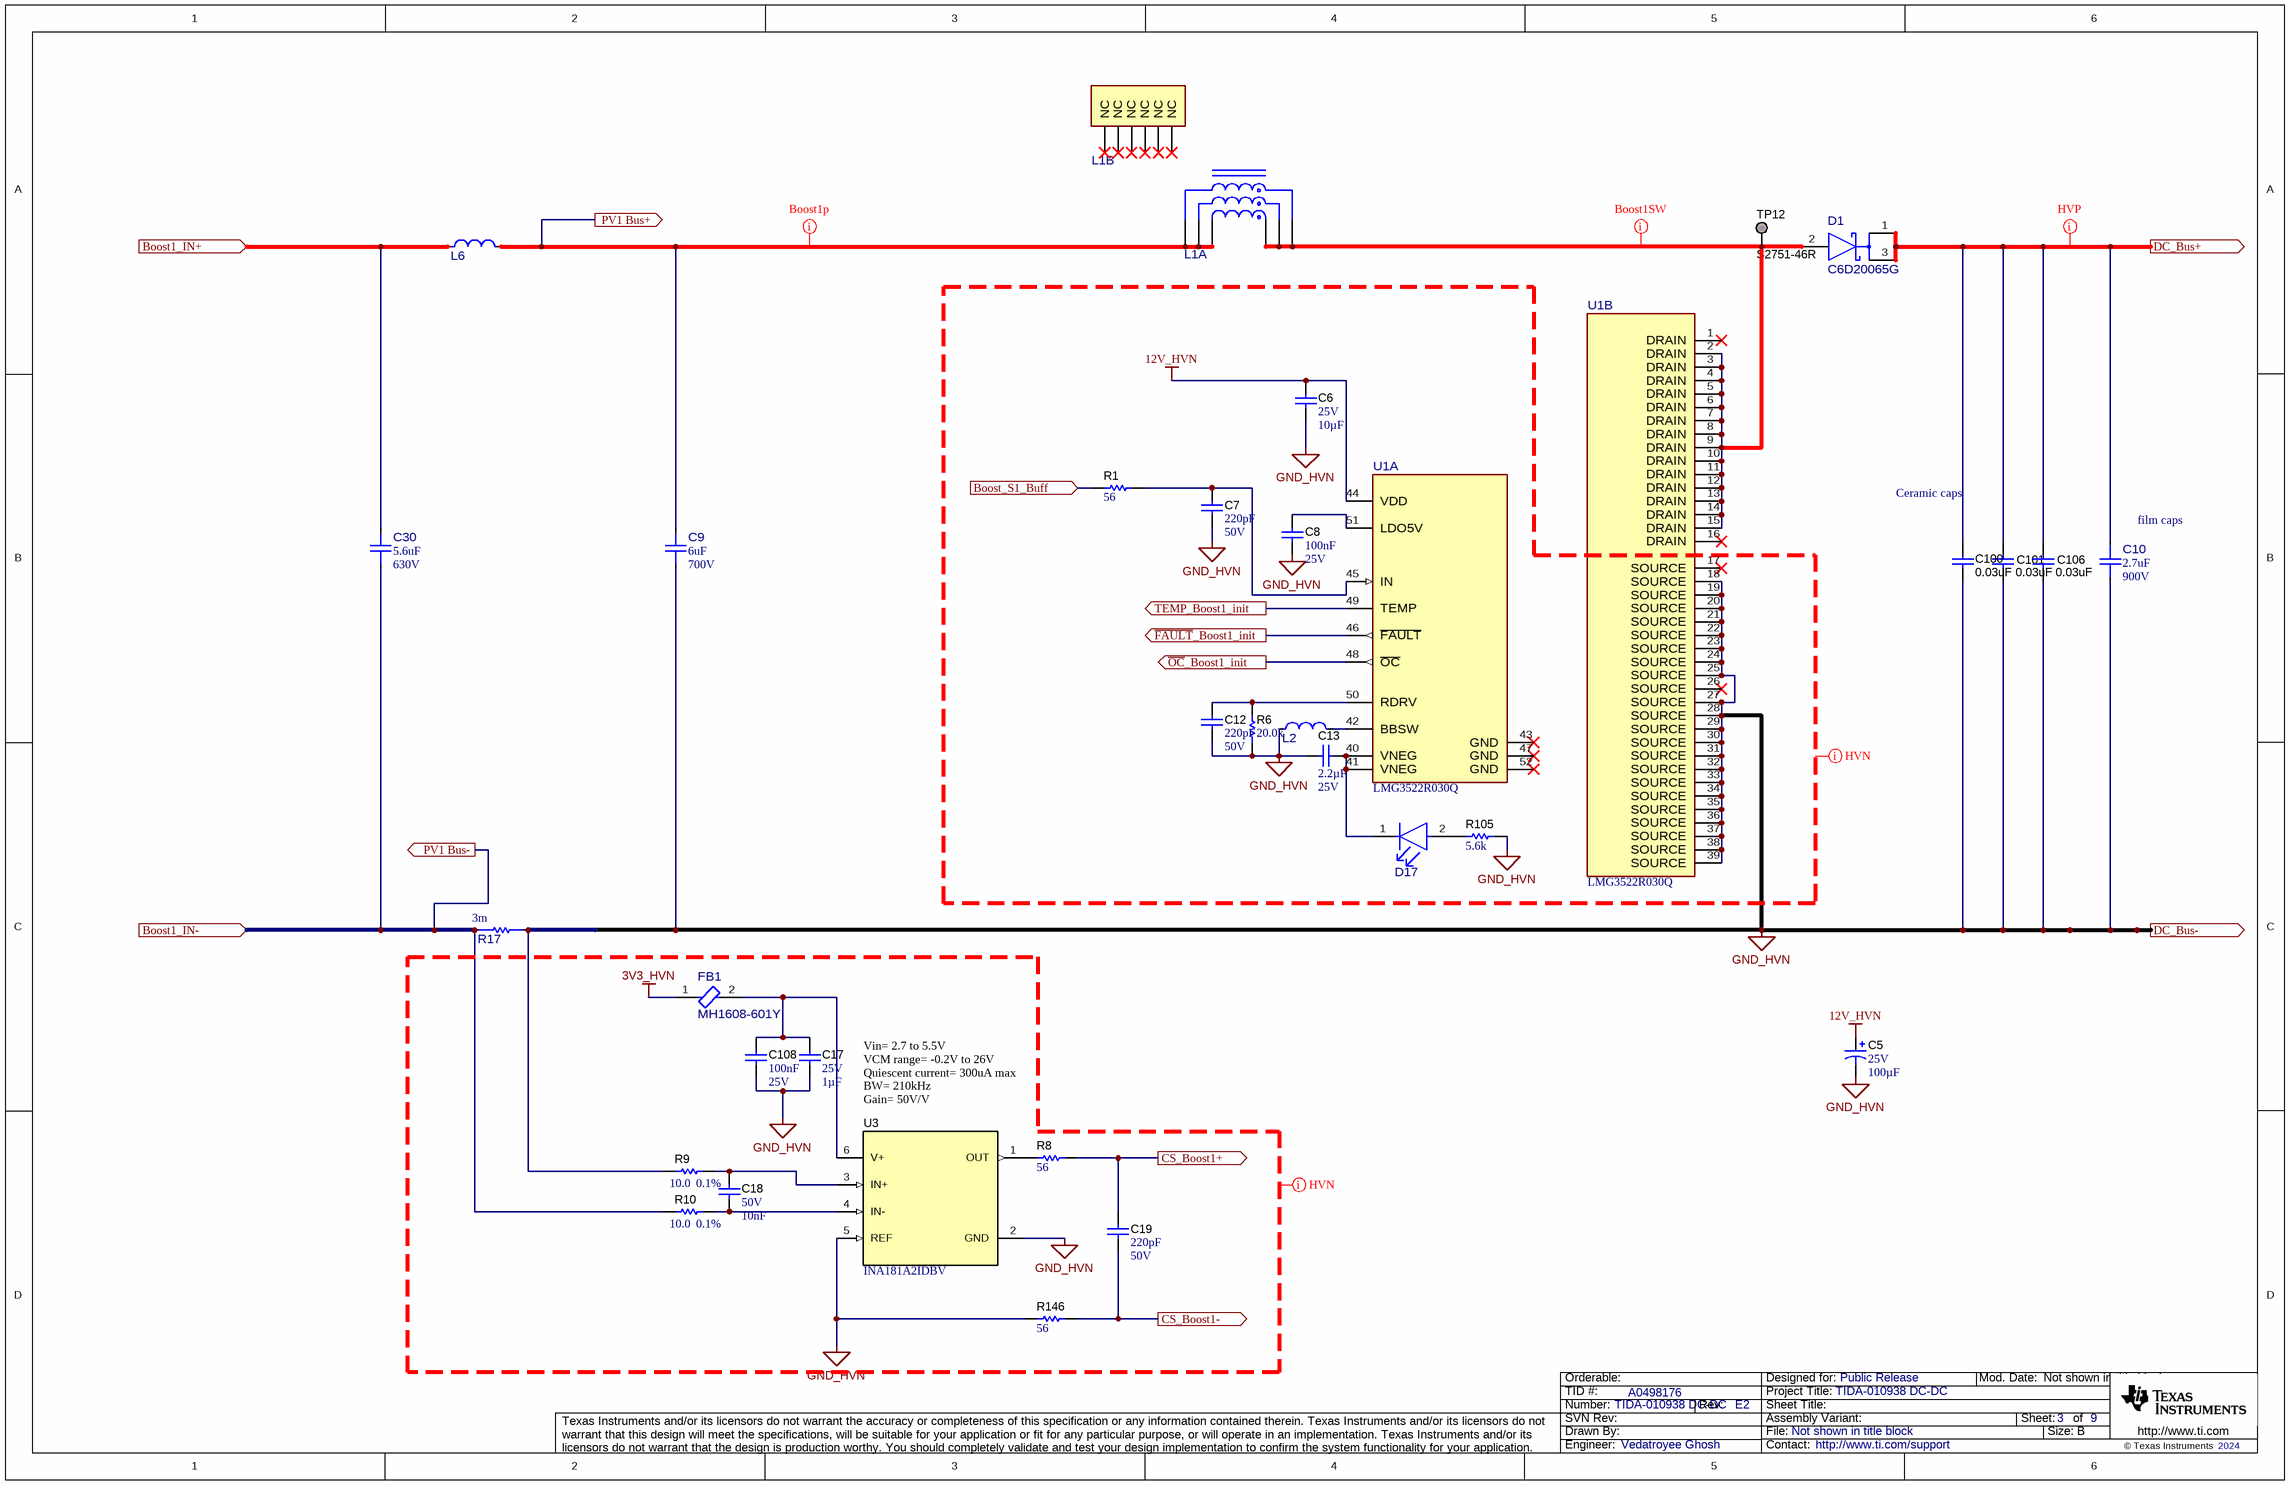
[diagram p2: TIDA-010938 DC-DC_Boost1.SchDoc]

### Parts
C5  VDC_V: 25V  ValueDisplayed: 100µF  [UWT_630x770]  (hidden comment: UWT1E101MCL1GS)
C6  VDC_V: 25V  ValueDisplayed: 10µF  [1206_180]  (hidden comment: TMK316AB7106KLHT)
C7  Cap_F: 220pF  VDC_V: 50V  [0603]  (hidden comment: GRM188R71H221KA01D)
C8  Cap_F: 100nF  VDC_V: 25V  [0603]  (hidden comment: 06033C104JAT2A)
C9  ValueDisplayed: 6uF  VDC_V: 700V  [FP-C4AUJBU4600M18J_RADIAL-MFG]  (hidden comment: C4AUJBU4600M18J)
C10  ValueDisplayed: 2.7uF  VDC_V: 900V  [FP-C4AKOBU4270A3YJ_RADIAL-MFG]  (hidden comment: C4AKOBU4270A3YJ)
C12  Cap_F: 220pF  VDC_V: 50V  [0603]  (hidden comment: GRM188R71H221KA01D)
C13  Cap_F: 2.2µF  VDC_V: 25V  [0805_HV]  (hidden comment: CGA4J3X7R1E225K125AB)
C17  VDC_V: 25V  ValueDisplayed: 1µF  [0603]  (hidden comment: TMK107BJ105KA-T)
C18  VDC_V: 50V  Cap_F: 10nF  [0603]  (hidden comment: 885012206089)
C19  Cap_F: 220pF  VDC_V: 50V  [0603]  (hidden comment: GRM188R71H221KA01D)
C30  ValueDisplayed: 5.6uF  VDC_V: 630V  [FP-R533R456050P0M_RADIAL-MFG]  (hidden comment: R533R456050P0M)
C100  ValueDisplayed: 0.03uF  [1812_254]  (hidden comment: C1812C303KDGLCAUTO)
C101  ValueDisplayed: 0.03uF  [1812_254]  (hidden comment: C1812C303KDGLCAUTO)
C106  ValueDisplayed: 0.03uF  [1812_254]  (hidden comment: C1812C303KDGLCAUTO)
C108  Cap_F: 100nF  VDC_V: 25V  [0603]  (hidden comment: 06033C104JAT2A)
D1  C6D20065G  [FP-C6D20065G_TO263-2-MFG]
D17  KG DELLS1.22-JGKH-24  [FP-KG DELLS1.22-JGKH-24_0603-MFG]  (value not drawn)
FB1  MH1608-601Y  [FP-MH1608-601Y_0603-MFG]
L1  145451  [FP-145451_PTH_IND_50MM0_50MM0-MFG]  (value not drawn)  (parts A,B of 2)
L2  SDEM20161T-4R7MS  [FP-SDEM20161T-4R7MS_SMD2-MFG]  (value not drawn)
L6  SRP1513CA-220M  [FP-SRP1513CA-220M_SMD2-MFG]  (value not drawn)
R1  ValueDisplayed: 56  [0603]  (hidden comment: RG1608P-560-B-T5)
R6  ValueDisplayed: 20.0k  [0603]  (hidden comment: RC0603FR-0720KL)
R8  ValueDisplayed: 56  [0603]  (hidden comment: RG1608P-560-B-T5)
R9  Tolerance_%: 0.1%  ValueDisplayed: 10.0  [0603]  (hidden comment: RT0603BRD0710RL)
R10  Tolerance_%: 0.1%  ValueDisplayed: 10.0  [0603]  (hidden comment: RT0603BRD0710RL)
R17  value 3m  [FP-CSS2H-2512K-3L00F_2512-MFG]  (hidden comment: CSS2H-2512K-3L00F)
R105  ValueDisplayed: 5.6k  [0603]  (hidden comment: RC0603JR-075K6L)
R146  ValueDisplayed: 56  [0603]  (hidden comment: RG1608P-560-B-T5)
TP12  S2751-46R  [Harwin_S2751-46R]  (no BOM)
U1  LMG3522R030Q  [RQS0052C-C01-MFG]  (parts A,B of 2)
U3  INA181A2IDBV  [DBV0006A_N]

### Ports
Boost1_IN+ (in), Boost1_IN- (in), Boost_S1_Buff (in), CS_Boost1+ (out), CS_Boost1- (out), DC_Bus+ (out), DC_Bus- (out), PV1 Bus+ (out), PV1 Bus- (out), TEMP_Boost1_init (out), ~{FAULT}_Boost1_init (out), ~{OC}_Boost1_init (out)

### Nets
3V3_HVN: FB1.1
12V_HVN: C5.1(+) C6.1 U1.44(VDD)
GND_HVN: C5.2(-) C6.2 C7.1 C8.1 C9.1 C10.2 C12.1 C13.2 C17.2 C100.2 C101.2 C106.2 C108.1 L2.1 R6.1 R9.1 R17.2 R105.1 R146.1 U1.18(SOURCE) U1.19(SOURCE) U1.20(SOURCE) U1.21(SOURCE) U1.22(SOURCE) U1.23(SOURCE) U1.24(SOURCE) U1.25(SOURCE) U1.27(SOURCE) U1.28(SOURCE) U1.29(SOURCE) U1.30(SOURCE) U1.31(SOURCE) U1.32(SOURCE) U1.33(SOURCE) U1.34(SOURCE) U1.35(SOURCE) U1.36(SOURCE) U1.37(SOURCE) U1.38(SOURCE) U1.39(SOURCE) U3.2(GND) U3.5(REF) ; port DC_Bus-  [project net DC_Bus-]
Boost1_IN+: C30.2 L6.1 ; port Boost1_IN+
Boost1_IN-: C30.1 R10.1 R17.1 ; port Boost1_IN-, port PV1 Bus-
Boost_S1_Buff: R1.1 ; port Boost_S1_Buff
CS_Boost1+: C19.2 R8.2 ; port CS_Boost1+
CS_Boost1-: C19.1 R146.2 ; port CS_Boost1-
DC_Bus+: C10.1 C100.1 C101.1 C106.1 D1.1(CATHODE) D1.3(CATHODE) ; port DC_Bus+
~{FAULT}_Boost1_init: U1.46(~{FAULT}) ; port ~{FAULT}_Boost1_init
~{OC}_Boost1_init: U1.48(~{OC}) ; port ~{OC}_Boost1_init
PV1 Bus+: C9.2 L1.4 L1.5 L1.6 L6.2 ; port PV1 Bus+
TEMP_Boost1_init: U1.49(TEMP) ; port TEMP_Boost1_init
NetC7_2: C7.2 R1.2 U1.45(IN)
NetC8_2: C8.2 U1.51(LDO5V)
NetC12_2: C12.2 R6.2 U1.50(RDRV)
NetC13_1: C13.1 D17.1(CATHODE) U1.40(VNEG) U1.41(VNEG)
NetC17_1: C17.1 C108.2 FB1.2 U3.6(V+)
NetC18_1: C18.1 R10.2 U3.4(IN-)
NetC18_2: C18.2 R9.2 U3.3(IN+)
NetD1_2: D1.2(ANODE) L1.1 L1.2 L1.3 TP12.1 U1.2(DRAIN) U1.3(DRAIN) U1.4(DRAIN) U1.5(DRAIN) U1.6(DRAIN) U1.7(DRAIN) U1.8(DRAIN) U1.9(DRAIN) U1.10(DRAIN) U1.11(DRAIN) U1.12(DRAIN) U1.13(DRAIN) U1.14(DRAIN) U1.15(DRAIN)
NetD17_2: D17.2(ANODE) R105.2
NetL2_2: L2.2 U1.42(BBSW)
NetR8_1: R8.1 U3.1(OUT)

Not connected (* = marked no-connect by the designer): L1 7(NC)* 8(NC)* 9(NC)* 10(NC)* 11(NC)* 12(NC)*; U1 1(DRAIN)* 16(DRAIN)* 17(SOURCE)* 26(SOURCE)* 43(GND)* 47(GND)* 52(GND)*

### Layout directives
net class HVN: 3V3_HVN, 12V_HVN, GND_HVN
net class Boost1SW: NetD1_2
net class HVP: DC_Bus+
net class Boost1p: PV1 Bus+

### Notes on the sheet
- Ceramic caps
- (near C10) film caps
- Vin= 2.7 to 5.5V
  VCM range= -0.2V to 26V
  Quiescent current= 300uA max
  BW= 210kHz
  Gain= 50V/V

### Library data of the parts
C5 = CMP-0081462-1: as C144 on sheet TIDA-010938 DCDC_Top
C6 = CMP-0750154-1: CAP, CERM, 10 µF, 25 V,+/- 10%, X7R, AEC-Q200 Grade 1, 1206; Manufacturer: Taiyo Yuden; AEC Qualified: Y; SizeZ_mm: 1.8; TaMax_C: 125°C; TaMin_C: -55°C; Cap_Case: 1206; Polarized: N; AEC Grade: 1; SizeY_mm: 1.6; Value: 10uF; SizeX_mm: 3.2; SizeAreaWB_mm2: 10.92; AEC Category: Q200; U/M: EA; SizeArea_mm2: 5.12
C7 C12 C19 = CMP-0007442-5: CAP, CERM, 220 pF, 50 V, +/- 10%, X7R, 0603; Manufacturer: MuRata; TaMin_C: -55°C; Polarized: N; SizeAreaWB_mm2: 4.68; Value1: Unknown; U/M: EA; Value: 220pF; TaMax_C: 125°C; SizeZ_mm: 1; SizeX_mm: 1.6; SizeY_mm: 0.8; SizeArea_mm2: 1.28; AEC Category: Q200
C8 C108 = CMP-0006752-5: as C1 on sheet TIDA-010938 DCDC_Top
C9 = CMP-0045101-1: 6 µF Film Capacitor 700V Polypropylene (PP), Metallized Radial; Manufacturer: KEMET; AEC Grade: Grade 2; AEC Qualified: Yes; Cap_F: 6µF; SizeZ_mm: 30.7mm; Tolerance_%: 5%; Value: 6µF
C10 = CMP-0045062-1: as C3 on sheet TIDA-010938 DCDC_Top
C13 = CMP-0007975-2: CAP, CERM, 2.2 uF, 25 V, +/- 10%, X7R, AEC-Q200 Grade 1, 0805; Manufacturer: TDK; TaMin_C: -55°C; Polarized: N; SizeAreaWB_mm2: 6.75; Value1: Unknown; U/M: EA; Value: 2.2uF; TaMax_C: 125°C; SizeZ_mm: 1.45; SizeX_mm: 2; SizeY_mm: 1.25; Cap_Case: 0805; SizeArea_mm2: 2.5; AEC Qualified: Y; AEC Grade: 1; AEC Category: Q200
C17 = CMP-0086152-1: CAP, CERM, 1 µF, 25 V,+/- 10%, X5R, 0603; Manufacturer: Taiyo Yuden; SizeAreaWB_mm2: 4.68; SizeZ_mm: 1; U/M: EA; Green_REACh: Passed; Value: 1uF; AEC Qualified: N; TaMax_C: 85°C; Green_Lifecycle: Active; AEC Category: Q200; SizeArea_mm2: 1.28; TaMin_C: -55°C; SizeY_mm: 0.8; SizeX_mm: 1.6
C18 = CMP-0750039-1: CAP, CERM, 0.01 µF, 50 V,+/- 10%, X7R, 0603; Manufacturer: Wurth Elektronik; Polarized: N; AEC Category: Q200; TaMax_C: 125°C; SizeAreaWB_mm2: 4.68; Value: 0.01uF; SizeArea_mm2: 1.28; SizeY_mm: 0.8; SizeZ_mm: 1; ValueDisplayed: 0.01µF; SizeX_mm: 1.6; U/M: EA; TaMin_C: -55°C
C30 = CMP-0045188-1: as C2 on sheet TIDA-010938 DCDC_Top
C100 C101 C106 = CMP-0009326-2: 0.03 µF ±10% 1000V (1kV) Ceramic Capacitor C0G, NP0 1812 (4532 Metric); Manufacturer: Kemet; Polarized: N; Value: 0.03uF; U/M: EA; Cap_F: 30nF; Value1: Unknown; TaMin_C: -55°C; TaMax_C: 125°C; Cap_Case: 1812; AEC Category: Q200; SizeArea_mm2: 14.4; SizeAreaWB_mm2: 23.1; SizeX_mm: 4.5; SizeY_mm: 3.2; SizeZ_mm: 2.54
D1 = CMP-0042032-1: Schottky Diode 650 V 20A Surface Mount TO-263-2; Manufacturer: Wolfspeed; AEC Qualified: No; SizeZ_mm: 4.82mm; TJmax_C: 175°C; Vf_V: 650V; Cap_F: 1153pF; Forward Current: 64A; Max Surge Forward Current: 135A; Peak Reverse Current: 5uA
D17 = CMP-0093310-1: as D14 on sheet TIDA-010938 DCDC_Top
FB1 = CMP-0037505-1: 600 Ohms @ 100 MHz 1 Power, Signal Line Ferrite Bead 0603 (1608 Metric) 1A 200mOhm; Manufacturer: Bourns; DCR_ohm: 0.2; SizeZ_mm: 1mm; AEC Qualified: No; Impedance At Frequency: 600Ω @ 100MHz; Test Frequency: 100MHz; Tolerance_%: 25%
L1 = CMP-0123113-1: PFC Inductor 120uH; Manufacturer: Bourns; AEC Qualified: No; DCR_ohm: 11.5m; Ind_H: 120µH; Isat: 20A; SizeZ_mm: 47.9mm; Test Frequency: 100kHz; Tolerance_%: 10%
L2 = CMP-0089347-1: 4.7µH Unshielded Inductor 1.1A 426mOhm Max 0806 (2016 Metric); Manufacturer: Cyntec; AEC Qualified: No; Material: Metal Dust; Isat: 1.26A; Test Frequency: 1MHz; DCR_ohm: 0.426; SizeZ_mm: 1mm; Tolerance_%: 20%
L6 = CMP-0095753-1: 22 µH Shielded Inductor 17 A 13.86mOhm Max Nonstandard; Manufacturer: Bourns; Isat: 22A; Value: 22uH; Shrouded: true; Material: Metal; Test Frequency: 100kHz; Q Factor: 40; AEC Qualified: Yes; Ind_H: 22µH; Self Resonant Frequency: 6MHz; Tolerance_%: 20%; DCR_ohm: 13.86m; SizeZ_mm: 13mm; Irms: 17A; AEC Grade: Grade 0
R1 R8 R146 = CMP-0023572-3: RES, 56, 0.1%, 0.1 W, 0603; Manufacturer: Susumu Co Ltd; Power_W: 100mW; TempCo: 25 ppm/C; Value_Code: 56R0; U/M: EA; Value: 56; SizeX_mm: 1.6; SizeY_mm: 0.8; SizeZ_mm: 1; Value2: 0.1W; SizeArea_mm2: 1.28; VDC_V: 75V; AEC Category: Q200
R6 = CMP-0022906-5: RES, 20.0 k, 1%, 0.1 W, 0603; Manufacturer: Yageo; Power_W: 100mW; TempCo: 100 ppm/C; Value_Code: 20k0; Value: 20.0k; EIA_Code: E96; Res_ohm: 20k; SizeX_mm: 1.6; SizeY_mm: 0.8; SizeZ_mm: 1; Value2: 0.1W; SizeArea_mm2: 1.28; AEC Qualified: N; VDC_V: 75V; AEC Category: Q200; SizeAreaWB_mm2: 4.68
R9 R10 = CMP-0023661-3: RES, 10.0, 0.1%, 0.1 W, 0603; Manufacturer: Yageo America; Power_W: 100mW; TempCo: 25 ppm/C; Value_Code: 10R0; U/M: EA; Value: 10.0; EIA_Code: E192; Res_ohm: 10; SizeX_mm: 1.6; SizeY_mm: 0.8; SizeZ_mm: 1; Value2: 0.1W; SizeArea_mm2: 1.28; VDC_V: 75V; AEC Category: Q200
R17 = CMP-0043791-1: Res Metal Strip 2512 0.003 Ohm 1% 4W ±75ppm/C Pad SMD Automotive T/R; Manufacturer: Bourns; AEC Grade: Grade 0; AEC Qualified: Yes; SizeZ_mm: 0.81mm; TempCo: 75ppm/°C
R105 = CMP-0025933-5: RES, 5.6 k, 5%, 0.1 W, 0603; Manufacturer: Yageo; Power_W: 100mW; TempCo: 100 ppm/C; Value_Code: 5k60; Value: 5.6k; EIA_Code: E24; SizeX_mm: 1.6; SizeY_mm: 0.8; SizeZ_mm: 1; Value2: 0.1W; SizeArea_mm2: 1.28; AEC Qualified: N; VDC_V: 75V; AEC Category: Q200; SizeAreaWB_mm2: 4.68
TP12 = CMP-0003968-1: Test Point, SMT; Manufacturer: Harwin
U1 = CMP-0089967-3: 650-V 30-mΩ GaN FET with Integrated Driver and Protection; Manufacturer: Texas Instruments; Standoff Height: 0mm; TJmax_C: +125°C; AEC Qualified: Yes; Nominal Supply Current: 16mA; Min Supply Voltage: 7.5V; SizeZ_mm: 1mm; AEC Category: Q200; Output Voltage: 520V; CompType: IC; Number Of Outputs: 1; Max Supply Voltage: 18V; AEC Grade: Grade 1
U3 = CMP-0013232-2: Bidirectional, Low- and High-Side Measurement, Multichannel, Voltage Output, Current-Sense Amplifier, DBV0006A (SOT-6); Manufacturer: Texas Instruments; SizeX_mm: 2.8; SizeY_mm: 2.9; CompType: IC; SizeZ_mm: 1.45; SizeArea_mm2: 8.12; SizeAreaWB_mm2: 14.82; U/M: EA

## Sheet TIDA-010938 DC-DC_Boost2.SchDoc
size 431 x 279 mm; Date: Not shown in title block; ApprovedBy: Not shown in title block; CheckedBy: Not shown in title block; Author: Not shown in title block; CompanyName: Not shown in title block; Engineer: Not shown in title block; Organization: Not shown in title block; Address1: Not shown in title block; Address2: Not shown in title block; Address3: Not shown in title block; Address4: Not shown in title block; DocumentNumber: 1; Revision: Use project parameter SCH_Rev; SheetNumber: 4; SheetTotal: 9; PageSetup: Record=PageOptions¦CenterHorizontal=True¦CenterVertical=True¦PrintScale=1.00¦XCorrection=1.00¦YCorrection=1.00¦PrintKind=0¦BorderSize=5000000¦LeftOffset=0¦BottomOffset=0¦Orientation=2¦PaperLength=1000¦PaperWidth=1000¦Scale=100¦PaperSource=15¦PrintQuality=600¦MediaType=1¦DitherType=10¦PaperKind=Letter¦PrintScaleMode=1
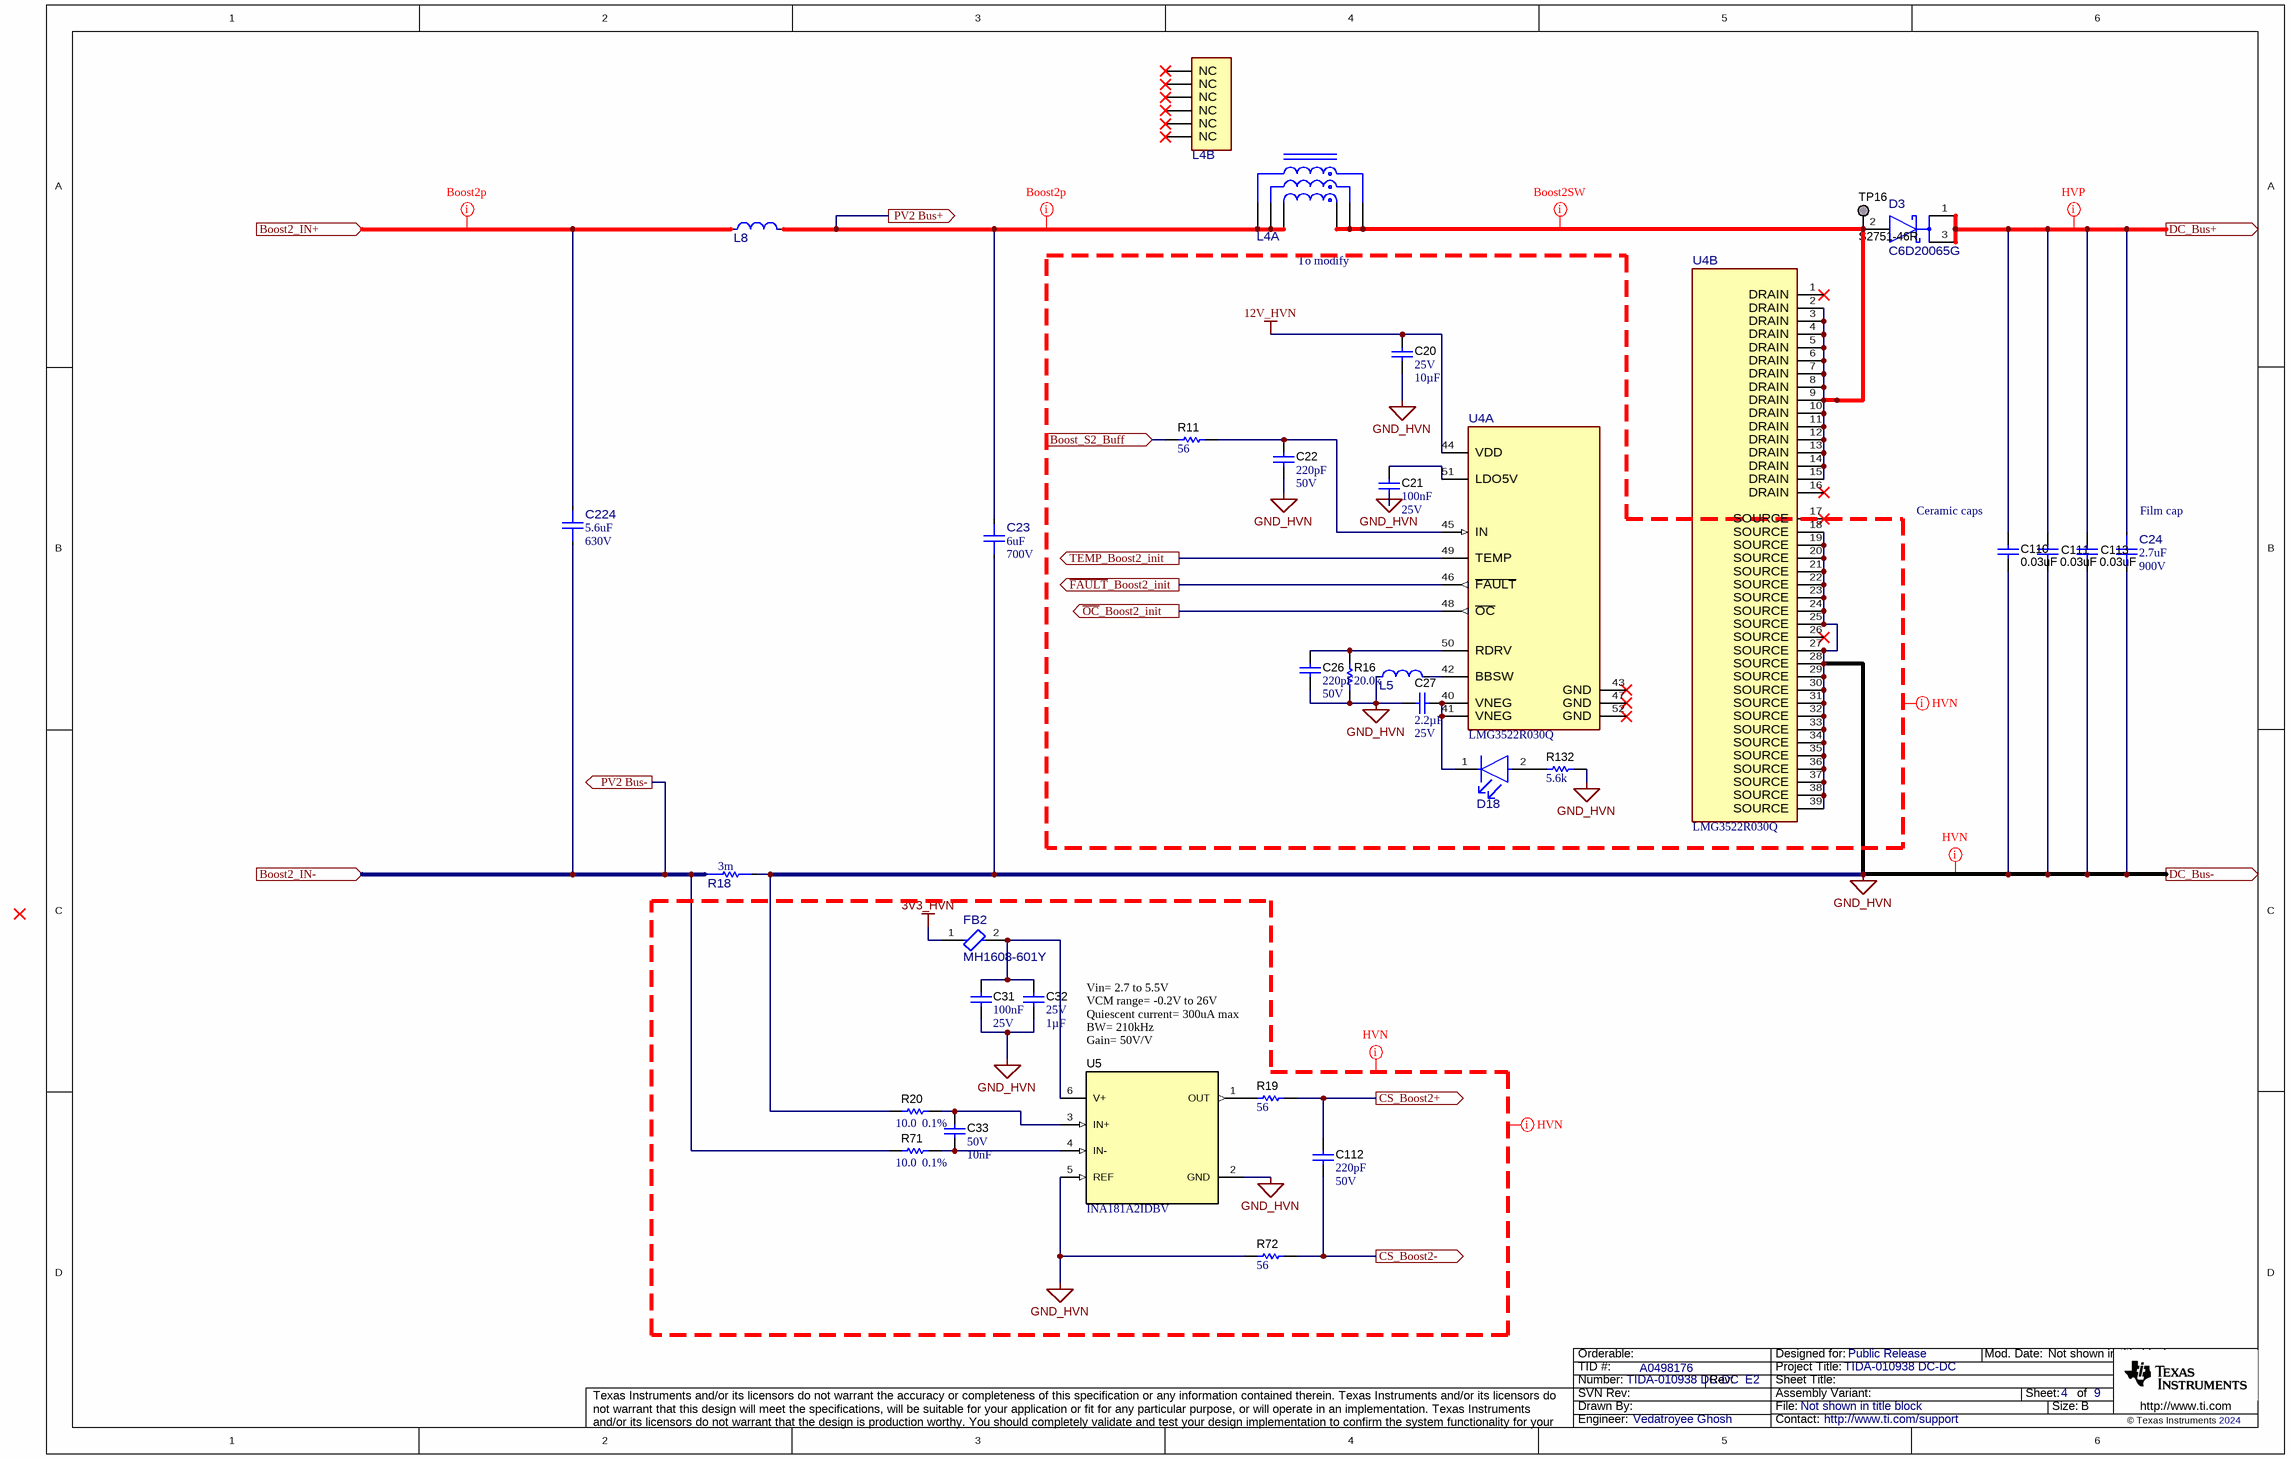
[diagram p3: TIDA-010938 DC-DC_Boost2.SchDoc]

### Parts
C20  VDC_V: 25V  ValueDisplayed: 10µF  [1206_180]  (hidden comment: TMK316AB7106KLHT)
C21  Cap_F: 100nF  VDC_V: 25V  [0603]  (hidden comment: 06033C104JAT2A)
C22  Cap_F: 220pF  VDC_V: 50V  [0603]  (hidden comment: GRM188R71H221KA01D)
C23  ValueDisplayed: 6uF  VDC_V: 700V  [FP-C4AUJBU4600M18J_RADIAL-MFG]  (hidden comment: C4AUJBU4600M18J)
C24  ValueDisplayed: 2.7uF  VDC_V: 900V  [FP-C4AKOBU4270A3YJ_RADIAL-MFG]  (hidden comment: C4AKOBU4270A3YJ)
C26  Cap_F: 220pF  VDC_V: 50V  [0603]  (hidden comment: GRM188R71H221KA01D)
C27  Cap_F: 2.2µF  VDC_V: 25V  [0805_HV]  (hidden comment: CGA4J3X7R1E225K125AB)
C31  Cap_F: 100nF  VDC_V: 25V  [0603]  (hidden comment: 06033C104JAT2A)
C32  VDC_V: 25V  ValueDisplayed: 1µF  [0603]  (hidden comment: TMK107BJ105KA-T)
C33  VDC_V: 50V  Cap_F: 10nF  [0603]  (hidden comment: 885012206089)
C110  ValueDisplayed: 0.03uF  [1812_254]  (hidden comment: C1812C303KDGLCAUTO)
C111  ValueDisplayed: 0.03uF  [1812_254]  (hidden comment: C1812C303KDGLCAUTO)
C112  Cap_F: 220pF  VDC_V: 50V  [0603]  (hidden comment: GRM188R71H221KA01D)
C113  ValueDisplayed: 0.03uF  [1812_254]  (hidden comment: C1812C303KDGLCAUTO)
C224  ValueDisplayed: 5.6uF  VDC_V: 630V  [FP-R533R456050P0M_RADIAL-MFG]  (hidden comment: R533R456050P0M)
D3  C6D20065G  [FP-C6D20065G_TO263-2-MFG]
D18  KG DELLS1.22-JGKH-24  [FP-KG DELLS1.22-JGKH-24_0603-MFG]  (value not drawn)
FB2  MH1608-601Y  [FP-MH1608-601Y_0603-MFG]
L4  145451  [FP-145451_PTH_IND_50MM0_50MM0-MFG]  (value not drawn)  (parts A,B of 2)
L5  SDEM20161T-4R7MS  [FP-SDEM20161T-4R7MS_SMD2-MFG]  (value not drawn)
L8  SRP1513CA-220M  [FP-SRP1513CA-220M_SMD2-MFG]  (value not drawn)
R11  ValueDisplayed: 56  [0603]  (hidden comment: RG1608P-560-B-T5)
R16  ValueDisplayed: 20.0k  [0603]  (hidden comment: RC0603FR-0720KL)
R18  value 3m  [FP-CSS2H-2512K-3L00F_2512-MFG]  (hidden comment: CSS2H-2512K-3L00F)
R19  ValueDisplayed: 56  [0603]  (hidden comment: RG1608P-560-B-T5)
R20  Tolerance_%: 0.1%  ValueDisplayed: 10.0  [0603]  (hidden comment: RT0603BRD0710RL)
R71  Tolerance_%: 0.1%  ValueDisplayed: 10.0  [0603]  (hidden comment: RT0603BRD0710RL)
R72  ValueDisplayed: 56  [0603]  (hidden comment: RG1608P-560-B-T5)
R132  ValueDisplayed: 5.6k  [0603]  (hidden comment: RC0603JR-075K6L)
TP16  S2751-46R  [Harwin_S2751-46R]  (no BOM)
U4  LMG3522R030Q  [RQS0052C-C01-MFG]  (parts A,B of 2)
U5  INA181A2IDBV  [DBV0006A_N]

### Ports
Boost2_IN+ (in), Boost2_IN- (in), Boost_S2_Buff (in), CS_Boost2+ (out), CS_Boost2- (out), DC_Bus+ (out), DC_Bus- (out), PV2 Bus+ (out), PV2 Bus- (out), TEMP_Boost2_init (out), ~{FAULT}_Boost2_init (out), ~{OC}_Boost2_init (out)

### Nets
3V3_HVN: FB2.1
12V_HVN: C20.1 U4.44(VDD)
GND_HVN: C20.2 C21.1 C22.1 C23.1 C24.2 C26.1 C27.2 C31.1 C32.2 C110.2 C111.2 C113.2 L5.1 R16.1 R18.2 R20.1 R72.1 R132.1 U4.18(SOURCE) U4.19(SOURCE) U4.20(SOURCE) U4.21(SOURCE) U4.22(SOURCE) U4.23(SOURCE) U4.24(SOURCE) U4.25(SOURCE) U4.27(SOURCE) U4.28(SOURCE) U4.29(SOURCE) U4.30(SOURCE) U4.31(SOURCE) U4.32(SOURCE) U4.33(SOURCE) U4.34(SOURCE) U4.35(SOURCE) U4.36(SOURCE) U4.37(SOURCE) U4.38(SOURCE) U4.39(SOURCE) U5.2(GND) U5.5(REF) ; port DC_Bus-  [project net DC_Bus-]
Boost2_IN+: C224.2 L8.1 ; port Boost2_IN+
Boost2_IN-: C224.1 R18.1 R71.1 ; port Boost2_IN-, port PV2 Bus-
Boost_S2_Buff: R11.1 ; port Boost_S2_Buff
CS_Boost2+: C112.2 R19.2 ; port CS_Boost2+
CS_Boost2-: C112.1 R72.2 ; port CS_Boost2-
DC_Bus+: C24.1 C110.1 C111.1 C113.1 D3.1(CATHODE) D3.3(CATHODE) ; port DC_Bus+
~{FAULT}_Boost2_init: U4.46(~{FAULT}) ; port ~{FAULT}_Boost2_init
~{OC}_Boost2_init: U4.48(~{OC}) ; port ~{OC}_Boost2_init
PV2 Bus+: C23.2 L4.4 L4.5 L4.6 L8.2 ; port PV2 Bus+
TEMP_Boost2_init: U4.49(TEMP) ; port TEMP_Boost2_init
NetC21_2: C21.2 U4.51(LDO5V)
NetC22_2: C22.2 R11.2 U4.45(IN)
NetC26_2: C26.2 R16.2 U4.50(RDRV)
NetC27_1: C27.1 D18.1(CATHODE) U4.40(VNEG) U4.41(VNEG)
NetC31_2: C31.2 C32.1 FB2.2 U5.6(V+)
NetC33_1: C33.1 R71.2 U5.4(IN-)
NetC33_2: C33.2 R20.2 U5.3(IN+)
NetD3_2: D3.2(ANODE) L4.1 L4.2 L4.3 TP16.1 U4.2(DRAIN) U4.3(DRAIN) U4.4(DRAIN) U4.5(DRAIN) U4.6(DRAIN) U4.7(DRAIN) U4.8(DRAIN) U4.9(DRAIN) U4.10(DRAIN) U4.11(DRAIN) U4.12(DRAIN) U4.13(DRAIN) U4.14(DRAIN) U4.15(DRAIN)
NetD18_2: D18.2(ANODE) R132.2
NetL5_2: L5.2 U4.42(BBSW)
NetR19_1: R19.1 U5.1(OUT)

Not connected (* = marked no-connect by the designer): L4 7(NC)* 8(NC)* 9(NC)* 10(NC)* 11(NC)* 12(NC)*; U4 1(DRAIN)* 16(DRAIN)* 17(SOURCE)* 26(SOURCE)* 43(GND)* 47(GND)* 52(GND)*

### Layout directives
net class HVN: 3V3_HVN, 12V_HVN, DC_Bus-, GND_HVN
net class Boost2SW: NetD3_2
net class HVP: DC_Bus+
net class Boost2p: Boost2_IN+, PV2 Bus+

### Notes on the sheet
- To modify
- (near C110) Ceramic caps
- (near C24) Film cap
- Vin= 2.7 to 5.5V
  VCM range= -0.2V to 26V
  Quiescent current= 300uA max
  BW= 210kHz
  Gain= 50V/V

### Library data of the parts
C20 = CMP-0750154-1: as C6 on sheet TIDA-010938 DC-DC_Boost1
C21 C31 = CMP-0006752-5: as C1 on sheet TIDA-010938 DCDC_Top
C22 C26 C112 = CMP-0007442-5: as C7 on sheet TIDA-010938 DC-DC_Boost1
C23 = CMP-0045101-1: as C9 on sheet TIDA-010938 DC-DC_Boost1
C24 = CMP-0045062-1: as C3 on sheet TIDA-010938 DCDC_Top
C27 = CMP-0007975-2: as C13 on sheet TIDA-010938 DC-DC_Boost1
C32 = CMP-0086152-1: as C17 on sheet TIDA-010938 DC-DC_Boost1
C33 = CMP-0750039-1: as C18 on sheet TIDA-010938 DC-DC_Boost1
C110 C111 C113 = CMP-0009326-2: as C100 on sheet TIDA-010938 DC-DC_Boost1
C224 = CMP-0045188-1: as C2 on sheet TIDA-010938 DCDC_Top
D3 = CMP-0042032-1: as D1 on sheet TIDA-010938 DC-DC_Boost1
D18 = CMP-0093310-1: as D14 on sheet TIDA-010938 DCDC_Top
FB2 = CMP-0037505-1: as FB1 on sheet TIDA-010938 DC-DC_Boost1
L4 = CMP-0123113-1: as L1 on sheet TIDA-010938 DC-DC_Boost1
L5 = CMP-0089347-1: as L2 on sheet TIDA-010938 DC-DC_Boost1
L8 = CMP-0095753-1: as L6 on sheet TIDA-010938 DC-DC_Boost1
R11 R19 R72 = CMP-0023572-3: as R1 on sheet TIDA-010938 DC-DC_Boost1
R16 = CMP-0022906-5: as R6 on sheet TIDA-010938 DC-DC_Boost1
R18 = CMP-0043791-1: as R17 on sheet TIDA-010938 DC-DC_Boost1
R20 R71 = CMP-0023661-3: as R9 on sheet TIDA-010938 DC-DC_Boost1
R132 = CMP-0025933-5: as R105 on sheet TIDA-010938 DC-DC_Boost1
TP16 = CMP-0003968-1: Test Point, SMT; Manufacturer: Harwin
U4 = CMP-0089967-3: as U1 on sheet TIDA-010938 DC-DC_Boost1
U5 = CMP-0013232-2: as U3 on sheet TIDA-010938 DC-DC_Boost1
